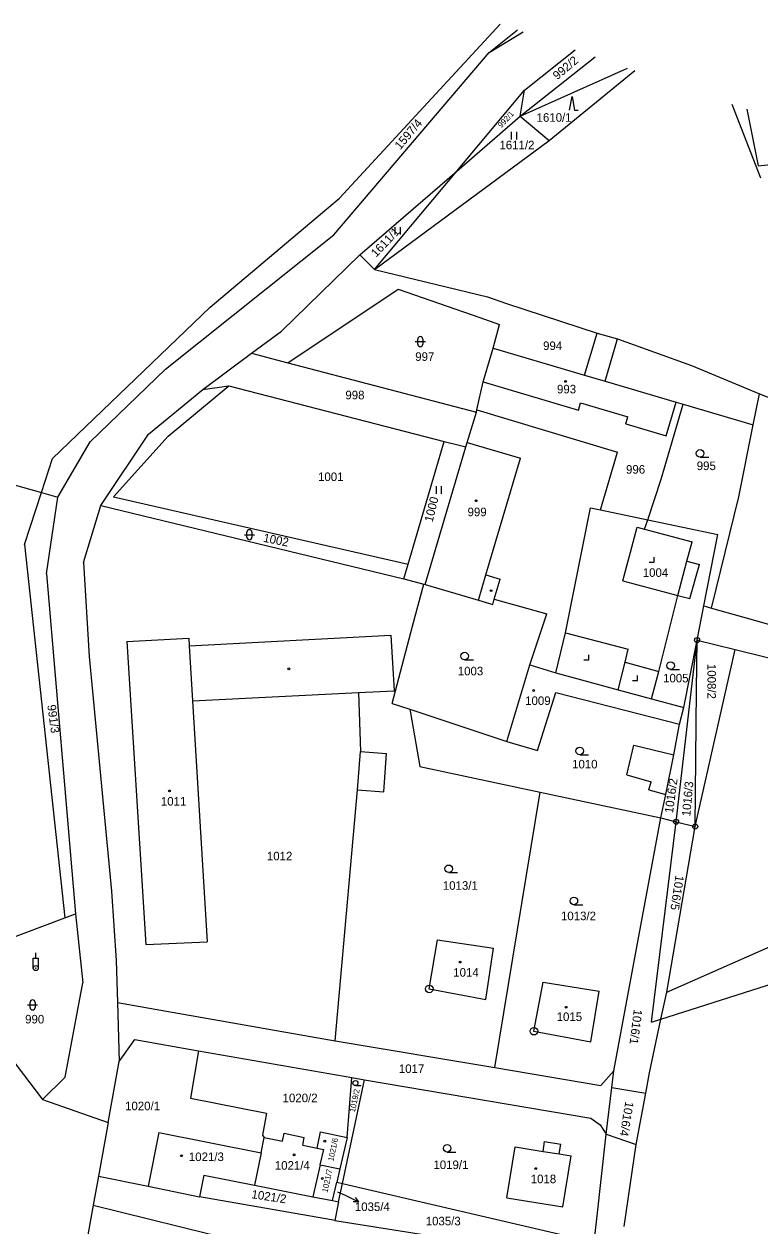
# Model space of a CAD drawing. Extents: x -779596 to -776743, y -1030330 to -1024513.
# Drawn here: x -777278.3 to -777132.1, y -1025802.5 to -1025563.8 of the extents above; entities that cross this region are included whole.
import ezdxf

# ---------------------------------------------------------------- set-up
doc = ezdxf.new("R2010")
doc.units = 0
for name, color, linetype in [('hranice parcel', 7, 'Continuous'), ('hranice vnitřní', 7, 'Continuous'), ('kultura', 7, 'Continuous'), ('Kód', 7, 'Continuous'), ('č_ parcel šipka', 7, 'Continuous'), ('č_pacel stav_', 7, 'Continuous'), ('č_parcel poz_', 7, 'Continuous')]:
    doc.layers.add(name, color=color, linetype=linetype)

msp = doc.modelspace()

# ---------------------------------------------------------------- linework, layer by layer
at = {"layer": 'hranice parcel'}
for points in [[(-777215.66, -1025598.35), (-777183.724, -1025563.793)], [(-777185.93, -1025569.47), (-777180.301, -1025564.976)], [(-777185.93, -1025569.47), (-777179.155, -1025565.373)], [(-777178.89, -1025576.91), (-777168.826, -1025568.945)], [(-777216.76, -1025605.67), (-777185.93, -1025569.47)], [(-777179.73, -1025582.12), (-777164.883, -1025570.309)], [(-777179.73, -1025582.12), (-777158.438, -1025572.537)], [(-777173.99, -1025586.95), (-777156.974, -1025573.044)], [(-777192.34, -1025593), (-777178.89, -1025576.91)], [(-777179.73, -1025582.12), (-777178.89, -1025576.91)], [(-777137.747, -1025579.693), (-777132.03, -1025594.32)], [(-777134.763, -1025580.725), (-777132.5, -1025591.97)], [(-777192.34, -1025593), (-777179.73, -1025582.12)], [(-777179.73, -1025582.12), (-777173.99, -1025586.95)], [(-777208.68, -1025612.54), (-777173.99, -1025586.95)], [(-777132.5, -1025591.97), (-777109.452, -1025589.478)], [(-777211.6, -1025609.61), (-777192.34, -1025593)], [(-777208.68, -1025612.54), (-777192.34, -1025593)], [(-777241.31, -1025620.04), (-777215.66, -1025598.35)], [(-777250.17, -1025632.3), (-777216.76, -1025605.67)], [(-777227.16, -1025624.78), (-777211.6, -1025609.61)], [(-777211.6, -1025609.61), (-777208.68, -1025612.54)], [(-777208.68, -1025612.54), (-777186.27, -1025617.96)], [(-777225.92, -1025631.05), (-777203.98, -1025616.47)], [(-777203.98, -1025616.47), (-777187.79, -1025622.09)], [(-777186.27, -1025617.96), (-777182.47, -1025619.3)], [(-777182.47, -1025619.3), (-777164.48, -1025625.17)], [(-777272.62, -1025650.04), (-777241.31, -1025620.04)], [(-777187.79, -1025622.09), (-777183.87, -1025623.46)], [(-777185.09, -1025628.15), (-777183.87, -1025623.46)], [(-777233.09, -1025629.17), (-777227.16, -1025624.78)], [(-777164.48, -1025625.17), (-777160.4, -1025626.29)], [(-777160.4, -1025626.29), (-777145.73, -1025631.61)], [(-777187.08, -1025634.86), (-777185.09, -1025628.15)], [(-777185.09, -1025628.15), (-777166.98, -1025633.51)], [(-777242.77, -1025636.34), (-777233.09, -1025629.17)], [(-777233.09, -1025629.17), (-777225.92, -1025631.05)], [(-777225.92, -1025631.05), (-777188.45, -1025640.88)], [(-777265.15, -1025646.76), (-777250.17, -1025632.3)], [(-777166.98, -1025633.51), (-777162.9, -1025634.71)], [(-777145.73, -1025631.61), (-777132.24, -1025637.24)], [(-777249.64, -1025645.65), (-777237.63, -1025635.67)], [(-777242.77, -1025636.34), (-777237.63, -1025635.67)], [(-777237.63, -1025635.67), (-777194.85, -1025646.66)], [(-777188.34, -1025640.39), (-777187.08, -1025634.86)], [(-777187.08, -1025634.86), (-777168.18, -1025640.45)], [(-777162.9, -1025634.71), (-777148.77, -1025638.89)], [(-777253.58, -1025645.24), (-777242.77, -1025636.34)], [(-777133.48, -1025643.41), (-777132.24, -1025637.24)], [(-777132.24, -1025637.24), (-777125.48, -1025639.9)], [(-777337.14, -1025639.31), (-777274.83, -1025656.83)], [(-777188.45, -1025640.88), (-777188.34, -1025640.39)], [(-777188.34, -1025640.39), (-777160.43, -1025648.78)], [(-777168.18, -1025640.45), (-777167.76, -1025639)], [(-777167.76, -1025639), (-777158.36, -1025641.78)], [(-777151.75, -1025654.2), (-777147.37, -1025639.31)], [(-777150.75, -1025645.59), (-777148.77, -1025638.89)], [(-777148.77, -1025638.89), (-777147.37, -1025639.31)], [(-777147.37, -1025639.31), (-777133.48, -1025643.41)], [(-777190.28, -1025646.92), (-777188.45, -1025640.88)], [(-777158.78, -1025643.21), (-777158.36, -1025641.78)], [(-777263, -1025659.39), (-777253.58, -1025645.24)], [(-777158.78, -1025643.21), (-777150.75, -1025645.59)], [(-777136.36, -1025657.7), (-777133.48, -1025643.41)], [(-777271.57, -1025657.75), (-777265.15, -1025646.76)], [(-777260.52, -1025657.69), (-777249.64, -1025645.65)], [(-777202.01, -1025671.08), (-777194.85, -1025646.66)], [(-777198.59, -1025675.09), (-777190.53, -1025647.76)], [(-777194.85, -1025646.66), (-777191.86, -1025647.42)], [(-777191.86, -1025647.42), (-777190.53, -1025647.76)], [(-777190.53, -1025647.76), (-777190.28, -1025646.92)], [(-777274.83, -1025656.83), (-777272.62, -1025650.04)], [(-777163.82, -1025660.25), (-777160.43, -1025648.78)], [(-777154.41, -1025662.24), (-777151.75, -1025654.2)], [(-777278.19, -1025667.17), (-777274.83, -1025656.83)], [(-777274.83, -1025656.83), (-777271.57, -1025657.75)], [(-777273.83, -1025672.95), (-777271.57, -1025657.75)], [(-777266.45, -1025670.7), (-777263, -1025659.39)], [(-777263, -1025659.39), (-777202.86, -1025673.99)], [(-777260.52, -1025657.69), (-777202.01, -1025671.08)], [(-777170.76, -1025684.68), (-777165.76, -1025659.84)], [(-777165.76, -1025659.84), (-777163.82, -1025660.25)], [(-777141.73, -1025679.77), (-777136.36, -1025657.7)], [(-777163.82, -1025660.25), (-777154.41, -1025662.24)], [(-777155.03, -1025664.1), (-777154.41, -1025662.24)], [(-777154.41, -1025662.24), (-777140.51, -1025665.18)], [(-777155.03, -1025664.1), (-777145.6, -1025666.6)], [(-777146.63, -1025670.46), (-777145.6, -1025666.6)], [(-777143.29, -1025679.33), (-777140.51, -1025665.18)], [(-777278.19, -1025667.17), (-777270.15, -1025741.27)], [(-777266.45, -1025670.7), (-777265.37, -1025689.4)], [(-777202.86, -1025673.99), (-777202.01, -1025671.08)], [(-777146.63, -1025670.46), (-777144.17, -1025671.11)], [(-777146.07, -1025677.86), (-777144.17, -1025671.11)], [(-777273.83, -1025672.95), (-777268.04, -1025740.48)], [(-777202.86, -1025673.99), (-777199.6, -1025674.83)], [(-777201.1, -1025683.35), (-777198.88, -1025675.01)], [(-777199.6, -1025674.83), (-777198.88, -1025675.01)], [(-777198.88, -1025675.01), (-777198.59, -1025675.09)], [(-777198.59, -1025675.09), (-777188.03, -1025678.21)], [(-777188.03, -1025678.21), (-777185.2, -1025679.05)], [(-777185.2, -1025679.05), (-777184.91, -1025677.99)], [(-777184.91, -1025677.99), (-777174.47, -1025680.93)], [(-777152.21, -1025692.36), (-777148.43, -1025677.24)], [(-777148.43, -1025677.24), (-777146.07, -1025677.86)], [(-777177.8, -1025691.03), (-777174.47, -1025680.93)], [(-777144.62, -1025686.12), (-777143.29, -1025679.33)], [(-777143.29, -1025679.33), (-777141.73, -1025679.77)], [(-777141.73, -1025679.77), (-777135.62, -1025681.49)], [(-777204.53, -1025696.2), (-777201.1, -1025683.35)], [(-777135.62, -1025681.49), (-777098.98, -1025691.81)], [(-777257.88, -1025686.39), (-777245.56, -1025685.74)], [(-777245.56, -1025685.74), (-777245.47, -1025687.29)], [(-777245.47, -1025687.29), (-777205.42, -1025685.14)], [(-777205.42, -1025685.14), (-777204.77, -1025696.21)], [(-777172.67, -1025692.61), (-777170.76, -1025684.68)], [(-777148.78, -1025722.2), (-777144.62, -1025686.12)], [(-777147.25, -1025699.51), (-777144.62, -1025686.12)], [(-777144.72, -1025696.07), (-777144.62, -1025686.12)], [(-777144.62, -1025686.12), (-777137.08, -1025687.98)], [(-777257.88, -1025686.39), (-777254.09, -1025746.58)], [(-777144.99, -1025723.15), (-777137.08, -1025687.98)], [(-777137.08, -1025687.98), (-777102.25, -1025696.58)], [(-777265.37, -1025689.4), (-777260.91, -1025736)], [(-777182.38, -1025706.25), (-777177.8, -1025691.03)], [(-777177.8, -1025691.03), (-777172.67, -1025692.61)], [(-777172.67, -1025692.61), (-777160.26, -1025695.98)], [(-777153.67, -1025697.77), (-777152.21, -1025692.36)], [(-777244.8, -1025698.17), (-777211.86, -1025696.56)], [(-777211.86, -1025696.56), (-777204.77, -1025696.21)], [(-777211.86, -1025696.56), (-777211.48, -1025708.28)], [(-777205.19, -1025698.69), (-777204.53, -1025696.2)], [(-777204.77, -1025696.21), (-777204.53, -1025696.2)], [(-777176.28, -1025708.08), (-777172.64, -1025696.53)], [(-777172.64, -1025696.53), (-777148.09, -1025702.79)], [(-777160.26, -1025695.98), (-777153.67, -1025697.77)], [(-777153.67, -1025697.77), (-777147.25, -1025699.51)], [(-777144.99, -1025723.15), (-777144.72, -1025696.07)], [(-777244.8, -1025698.17), (-777241.89, -1025746.05)], [(-777205.19, -1025698.69), (-777201.63, -1025699.87)], [(-777201.63, -1025699.87), (-777182.38, -1025706.25)], [(-777201.63, -1025699.87), (-777201.51, -1025700.57)], [(-777148.09, -1025702.79), (-777147.25, -1025699.51)], [(-777201.51, -1025700.57), (-777199.69, -1025711.23)], [(-777149.27, -1025708.92), (-777148.09, -1025702.79)], [(-777182.38, -1025706.25), (-777176.28, -1025708.08)], [(-777212.04, -1025715.89), (-777211.48, -1025708.28)], [(-777150.83, -1025716.81), (-777149.27, -1025708.92)], [(-777199.69, -1025711.23), (-777175.78, -1025716.32)], [(-777216.49, -1025765.68), (-777212.04, -1025715.89)], [(-777184.8, -1025771.03), (-777175.78, -1025716.32)], [(-777175.78, -1025716.32), (-777151.85, -1025721.42)], [(-777151.85, -1025721.42), (-777150.83, -1025716.81)], [(-777161.15, -1025771.63), (-777151.85, -1025721.42)], [(-777151.85, -1025721.42), (-777148.78, -1025722.2)], [(-777153.66, -1025762), (-777148.78, -1025722.2)], [(-777150.65, -1025756.05), (-777144.99, -1025723.15)], [(-777148.78, -1025722.2), (-777144.99, -1025723.15)], [(-777260.91, -1025736), (-777259.97, -1025749.78)], [(-777150.65, -1025756.05), (-777108.05, -1025737.22)], [(-777270.15, -1025741.27), (-777268.04, -1025740.48)], [(-777268.04, -1025740.48), (-777266.61, -1025754.21)], [(-777295.02, -1025750.59), (-777270.15, -1025741.27)], [(-777197.8, -1025755.4), (-777196.15, -1025745.63)], [(-777196.15, -1025745.63), (-777185.02, -1025747.32)], [(-777254.09, -1025746.58), (-777241.89, -1025746.05)], [(-777186.56, -1025757.47), (-777185.02, -1025747.32)], [(-777259.97, -1025749.78), (-777259.73, -1025758.1)], [(-777295.02, -1025750.59), (-777274.62, -1025777.35)], [(-777151.8, -1025761.41), (-777118.76, -1025750.88)], [(-777270.11, -1025772.9), (-777266.61, -1025754.21)], [(-777177.01, -1025763.79), (-777175.21, -1025754.03)], [(-777175.21, -1025754.03), (-777164.09, -1025755.81)], [(-777197.8, -1025755.4), (-777186.56, -1025757.47)], [(-777165.71, -1025765.93), (-777164.09, -1025755.81)], [(-777151.8, -1025761.41), (-777150.65, -1025756.05)], [(-777259.73, -1025758.1), (-777248.84, -1025760.01)], [(-777259.73, -1025758.1), (-777259.39, -1025769.79)], [(-777248.84, -1025760.01), (-777216.49, -1025765.68)], [(-777154.09, -1025772.08), (-777151.8, -1025761.41)], [(-777153.66, -1025762), (-777151.8, -1025761.41)], [(-777177.01, -1025763.79), (-777165.71, -1025765.93)], [(-777259.39, -1025769.79), (-777256.27, -1025765.47)], [(-777256.27, -1025765.47), (-777243.6, -1025767.69)], [(-777216.49, -1025765.68), (-777184.8, -1025771.03)], [(-777243.6, -1025767.69), (-777245.22, -1025777.08)], [(-777243.6, -1025767.69), (-777213.16, -1025773.01)], [(-777261.57, -1025781.89), (-777259.39, -1025769.79)], [(-777184.8, -1025771.03), (-777163.75, -1025774.59)], [(-777163.75, -1025774.59), (-777161.15, -1025771.63)], [(-777161.56, -1025774.96), (-777161.15, -1025771.63)], [(-777274.62, -1025777.35), (-777270.11, -1025772.9)], [(-777215.03, -1025794.01), (-777210.69, -1025773.43)], [(-777214.11, -1025784.92), (-777213.16, -1025773.01)], [(-777213.16, -1025773.01), (-777210.69, -1025773.43)], [(-777210.69, -1025773.43), (-777165.69, -1025781.09)], [(-777154.83, -1025776.1), (-777154.09, -1025772.08)], [(-777162.68, -1025784.25), (-777161.56, -1025774.96)], [(-777161.56, -1025774.96), (-777154.83, -1025776.1)], [(-777156.7, -1025786.28), (-777154.83, -1025776.1)], [(-777274.62, -1025777.35), (-777261.57, -1025781.89)], [(-777245.22, -1025777.08), (-777230.14, -1025780.06)], [(-777230.14, -1025780.06), (-777230.9, -1025784.45)], [(-777165.69, -1025781.09), (-777163.89, -1025782.36)], [(-777261.57, -1025781.89), (-777263.49, -1025792.57)], [(-777251.49, -1025783.91), (-777253.61, -1025794.59)], [(-777251.49, -1025783.91), (-777231.2, -1025787.96)], [(-777220.04, -1025787), (-777219.39, -1025783.76)], [(-777219.39, -1025783.76), (-777214.11, -1025784.92)], [(-777163.89, -1025782.36), (-777162.68, -1025784.25)], [(-777231.2, -1025787.96), (-777230.59, -1025784.88)], [(-777230.9, -1025784.45), (-777230.59, -1025784.88)], [(-777230.59, -1025784.88), (-777226.92, -1025785.64)], [(-777226.92, -1025785.64), (-777226.61, -1025784.06)], [(-777226.61, -1025784.06), (-777222.64, -1025784.92)], [(-777222.94, -1025786.42), (-777222.64, -1025784.92)], [(-777214.11, -1025784.92), (-777215.55, -1025791.11)], [(-777175.21, -1025787.65), (-777174.89, -1025785.68)], [(-777174.89, -1025785.68), (-777171.69, -1025786.2)], [(-777172.01, -1025788.17), (-777171.69, -1025786.2)], [(-777164.54, -1025801.08), (-777162.68, -1025784.25)], [(-777162.68, -1025784.25), (-777156.7, -1025786.28)], [(-777159.13, -1025802.56), (-777156.7, -1025786.28)], [(-777231.2, -1025787.96), (-777232.48, -1025794.37)], [(-777222.94, -1025786.42), (-777220.04, -1025787)], [(-777220.04, -1025787), (-777218.73, -1025787.31)], [(-777219.44, -1025790.34), (-777218.73, -1025787.31)], [(-777182.4, -1025796.86), (-777180.76, -1025786.75)], [(-777180.76, -1025786.75), (-777175.21, -1025787.65)], [(-777172.01, -1025788.17), (-777169.64, -1025788.56)], [(-777171.29, -1025798.67), (-777169.64, -1025788.56)], [(-777219.44, -1025790.34), (-777220.92, -1025796.66)], [(-777219.44, -1025790.34), (-777215.55, -1025791.11)], [(-777215.55, -1025791.11), (-777216.17, -1025793.74)], [(-777263.49, -1025792.57), (-777264.52, -1025798.33)], [(-777263.49, -1025792.57), (-777253.61, -1025794.59)], [(-777242.55, -1025792.38), (-777243.4, -1025796.69)], [(-777242.55, -1025792.38), (-777232.48, -1025794.37)], [(-777253.61, -1025794.59), (-777243.4, -1025796.69)], [(-777232.48, -1025794.37), (-777220.92, -1025796.66)], [(-777217.03, -1025797.44), (-777216.17, -1025793.74)], [(-777216.17, -1025793.74), (-777215.03, -1025794.01)], [(-777215.8, -1025797.69), (-777215.03, -1025794.01)], [(-777215.03, -1025794.01), (-777165.05, -1025805.7)], [(-777217.19, -1025801.26), (-777243.4, -1025796.69)], [(-777220.92, -1025796.66), (-777217.03, -1025797.44)], [(-777217.03, -1025797.44), (-777215.8, -1025797.69)], [(-777215.8, -1025797.69), (-777216.58, -1025801.37)], [(-777182.4, -1025796.86), (-777171.29, -1025798.67)], [(-777264.52, -1025798.33), (-777265.91, -1025806.08)], [(-777264.52, -1025798.33), (-777236.13, -1025805.36)], [(-777216.58, -1025801.37), (-777217.19, -1025801.26)], [(-777216.58, -1025801.37), (-777184.3, -1025806.5)], [(-777165.05, -1025805.7), (-777164.54, -1025801.08)]]:
    msp.add_lwpolyline(points, dxfattribs=at)
at = {"layer": 'hranice vnitřní'}
for points in [[(-777166.98, -1025633.51), (-777164.48, -1025625.17)], [(-777162.9, -1025634.71), (-777160.4, -1025626.29)], [(-777190.28, -1025646.92), (-777179.71, -1025650.01)], [(-777186.55, -1025673.2), (-777179.71, -1025650.01)], [(-777159.35, -1025674.34), (-777156.53, -1025663.7)], [(-777156.53, -1025663.7), (-777155.03, -1025664.1)], [(-777148.43, -1025677.24), (-777146.63, -1025670.46)], [(-777188.03, -1025678.21), (-777186.55, -1025673.2)], [(-777186.55, -1025673.2), (-777183.74, -1025674.04)], [(-777184.91, -1025677.99), (-777183.74, -1025674.04)], [(-777159.35, -1025674.34), (-777148.43, -1025677.24)], [(-777170.76, -1025684.68), (-777158.3, -1025687.94)], [(-777245.47, -1025687.29), (-777244.8, -1025698.17)], [(-777158.93, -1025690.52), (-777158.3, -1025687.94)], [(-777160.26, -1025695.98), (-777158.93, -1025690.52)], [(-777158.93, -1025690.52), (-777152.21, -1025692.36)], [(-777158.57, -1025712.9), (-777157.17, -1025706.98)], [(-777157.17, -1025706.98), (-777149.27, -1025708.92)], [(-777211.48, -1025708.28), (-777206.28, -1025708.67)], [(-777206.84, -1025716.27), (-777206.28, -1025708.67)], [(-777158.57, -1025712.9), (-777153.75, -1025714.28)], [(-777154.2, -1025715.84), (-777153.75, -1025714.28)], [(-777212.04, -1025715.89), (-777206.84, -1025716.27)], [(-777154.2, -1025715.84), (-777150.83, -1025716.81)], [(-777175.21, -1025787.65), (-777172.01, -1025788.17)]]:
    msp.add_lwpolyline(points, dxfattribs=at)
at = {"layer": 'kultura'}
for points in [[(-777169.942, -1025580.88), (-777169.44, -1025578.199), (-777168.937, -1025580.88), (-777168.267, -1025580.88)], [(-777181.477, -1025586.715), (-777181.477, -1025585.215)], [(-777180.443, -1025586.715), (-777180.443, -1025585.215)], [(-777204.557, -1025605.615), (-777204.557, -1025604.115)], [(-777203.523, -1025605.615), (-777203.523, -1025604.115)], [(-777200.08, -1025627.36), (-777200.08, -1025626.36)], [(-777199.08, -1025626.36), (-777199.08, -1025627.36)], [(-777200.58, -1025626.86), (-777198.58, -1025626.86)], [(-777144.03, -1025649.81), (-777142.28, -1025649.81)], [(-777196.387, -1025657.065), (-777196.387, -1025655.565)], [(-777195.353, -1025657.065), (-777195.353, -1025655.565)], [(-777234.51, -1025665.2), (-777232.51, -1025665.2)], [(-777234.01, -1025665.7), (-777234.01, -1025664.7)], [(-777233.01, -1025664.7), (-777233.01, -1025665.7)], [(-777154.14, -1025670.66), (-777153.14, -1025670.66), (-777153.14, -1025669.66)], [(-777190.78, -1025690.05), (-777189.03, -1025690.05)], [(-777167.09, -1025690.07), (-777166.09, -1025690.07), (-777166.09, -1025689.07)], [(-777157.44, -1025694.14), (-777156.44, -1025694.14), (-777156.44, -1025693.14)], [(-777149.87, -1025691.94), (-777148.12, -1025691.94)], [(-777167.92, -1025708.88), (-777166.17, -1025708.88)], [(-777193.93, -1025732.29), (-777192.18, -1025732.29)], [(-777169.09, -1025738.67), (-777167.34, -1025738.67)], [(-777276.45, -1025751.26), (-777276.45, -1025749.26), (-777275.45, -1025749.26), (-777275.45, -1025751.26)], [(-777275.95, -1025749.26), (-777275.95, -1025748.26)], [(-777277.57, -1025758.58), (-777275.57, -1025758.58)], [(-777277.07, -1025759.08), (-777277.07, -1025758.08)], [(-777276.07, -1025758.08), (-777276.07, -1025759.08)], [(-777212.47, -1025774.59), (-777211.297, -1025774.59)], [(-777194.25, -1025787.79), (-777192.5, -1025787.79)]]:
    msp.add_lwpolyline(points, dxfattribs=at)
for centre, radius in [((-777170.74, -1025634.76), 0.175), ((-777144.03, -1025649.06), 0.75), ((-777188.5, -1025658.45), 0.175), ((-777185.53, -1025676.31), 0.175), ((-777190.78, -1025689.3), 0.75), ((-777149.87, -1025691.19), 0.75), ((-777225.69, -1025691.84), 0.175), ((-777177.07, -1025696.14), 0.175), ((-777167.92, -1025708.13), 0.75), ((-777249.4, -1025716.08), 0.175), ((-777193.93, -1025731.54), 0.75), ((-777169.09, -1025737.92), 0.75), ((-777191.69, -1025750.06), 0.175), ((-777275.95, -1025751.26), 0.5), ((-777275.95, -1025751.26), 0.05), ((-777170.64, -1025759.04), 0.175), ((-777212.47, -1025774.088), 0.503), ((-777218.56, -1025785.63), 0.175), ((-777194.25, -1025787.04), 0.75), ((-777247, -1025788.52), 0.175), ((-777224.65, -1025788.34), 0.175), ((-777176.66, -1025791.07), 0.175), ((-777219.04, -1025793.04), 0.175)]:
    msp.add_circle(centre, radius, dxfattribs=at)
for centre, start, end in [((-777199.58, -1025626.36), 0.101, 180.00143), ((-777199.58, -1025627.36), 180.10243, 0.00286), ((-777233.51, -1025664.7), 0.101, 180.00143), ((-777233.51, -1025665.7), 180.10243, 0.00286), ((-777276.57, -1025758.08), 0.101, 180.00143), ((-777276.57, -1025759.08), 180.10243, 0.00286)]:
    msp.add_arc(centre, 0.5, start, end, dxfattribs=at)
at = {"layer": 'Kód'}
for centre, radius in [((-777144.62, -1025686.12), 0.5), ((-777144.62, -1025686.12), 0.032), ((-777148.78, -1025722.2), 0.5), ((-777148.78, -1025722.2), 0.032), ((-777144.99, -1025723.15), 0.5), ((-777144.99, -1025723.15), 0.032), ((-777197.8, -1025755.4), 0.75), ((-777197.8, -1025755.4), 0.032), ((-777177.01, -1025763.79), 0.75), ((-777177.01, -1025763.79), 0.032)]:
    msp.add_circle(centre, radius, dxfattribs=at)
at = {"layer": 'č_ parcel šipka'}
for points in [[(-777216.01, -1025795.67), (-777214.53, -1025796.38)], [(-777214.53, -1025796.38), (-777211.827, -1025797.68)], [(-777212.512, -1025796.796), (-777211.827, -1025797.68), (-777212.945, -1025797.697)]]:
    msp.add_lwpolyline(points, dxfattribs=at)

# ---------------------------------------------------------------- texts
msp.add_text('1035/4', height=1.7, dxfattribs=at).set_placement((-777212.579, -1025799.5))
at = {"layer": 'č_pacel stav_'}
for s, p in [('993', (-777172.44, -1025637.14)), ('999', (-777190.2, -1025661.53)), ('1004', (-777155.41, -1025673.58)), ('1009', (-777178.76, -1025699.01)), ('1011', (-777251.1, -1025718.99)), ('1014', (-777193.04, -1025752.97)), ('1015', (-777172.51, -1025761.77)), ('1021/3', (-777245.539, -1025789.58)), ('1021/4', (-777228.469, -1025791.29)), ('1018', (-777177.66, -1025793.98))]:
    msp.add_text(s, height=1.7, dxfattribs=at).set_placement(p)
for s, rotation, p in [('1021/6', 78.10062, (-777216.834, -1025789.682)), ('1021/7', 78.00062, (-777218.007, -1025795.891))]:
    msp.add_text(s, height=1.14, rotation=rotation, dxfattribs=at).set_placement(p)
at = {"layer": 'č_parcel poz_'}
for s, height, rotation, p in [('992/2', 1.7, 40.20032, (-777172.387, -1025574.959)), ('1597/4', 1.7, 49.8004, (-777203.563, -1025588.869)), ('992/1', 1.14, 47.20038, (-777183.48, -1025584.508)), ('1611/1', 1.7, 46.30037, (-777208.346, -1025610.218)), ('1000', 1.7, 76.10061, (-777197.156, -1025662.818)), ('1002', 1.7, 348.90278, (-777230.866, -1025666.593)), ('1008/2', 1.7, 270.00215, (-777142.571, -1025690.86)), ('991/3', 1.7, 277.80221, (-777273.665, -1025699.061)), ('1016/2', 1.7, 82.30066, (-777149.411, -1025720.596)), ('1016/3', 1.7, 84.90068, (-777145.971, -1025721.184)), ('1016/5', 1.7, 261.50208, (-777148.892, -1025732.757)), ('1016/1', 1.7, 262.90209, (-777157.177, -1025759.393)), ('1019/2', 1.14, 77.80062, (-777212.584, -1025779.968)), ('1016/4', 1.7, 260.30207, (-777158.847, -1025777.65)), ('1021/2', 1.7, 351.40279, (-777233.192, -1025796.945))]:
    msp.add_text(s, height=height, rotation=rotation, dxfattribs=at).set_placement(p)
for s, height, p in [('1610/1', 1.7, (-777176.49, -1025583.2)), ('1611/2', 1.7, (-777183.87, -1025588.67)), ('994', 1.7, (-777175.2, -1025628.52)), ('997', 1.7, (-777200.59, -1025630.68)), ('998', 1.7, (-777214.46, -1025638.31)), ('996', 1.7, (-777158.73, -1025653.08)), ('995', 1.7, (-777144.69, -1025652.37)), ('1001', 1.7, (-777219.89, -1025654.54)), ('1003', 1.7, (-777192.14, -1025693.13)), ('1005', 1.7, (-777151.37, -1025694.53)), ('1010', 1.7, (-777169.44, -1025711.61)), ('1012', 1.7, (-777230.05, -1025729.86)), ('1013/1', 1.7, (-777195.11, -1025735.71)), ('1013/2', 1.7, (-777171.65, -1025741.75)), ('990', 1.7, (-777278.05, -1025762.25)), ('1017', 1.7, (-777203.84, -1025772.09)), ('1020/2', 1.7, (-777226.929, -1025777.89)), ('1020/1', 1.7, (-777258.209, -1025779.49)), ('1019/1', 1.7, (-777196.979, -1025791.17)), ('1035/4', 0.1, (-777216.009, -1025795.47)), ('1035/3', 1.7, (-777198.509, -1025802.35))]:
    msp.add_text(s, height=height, dxfattribs=at).set_placement(p)

doc.saveas('drawing.dxf')
